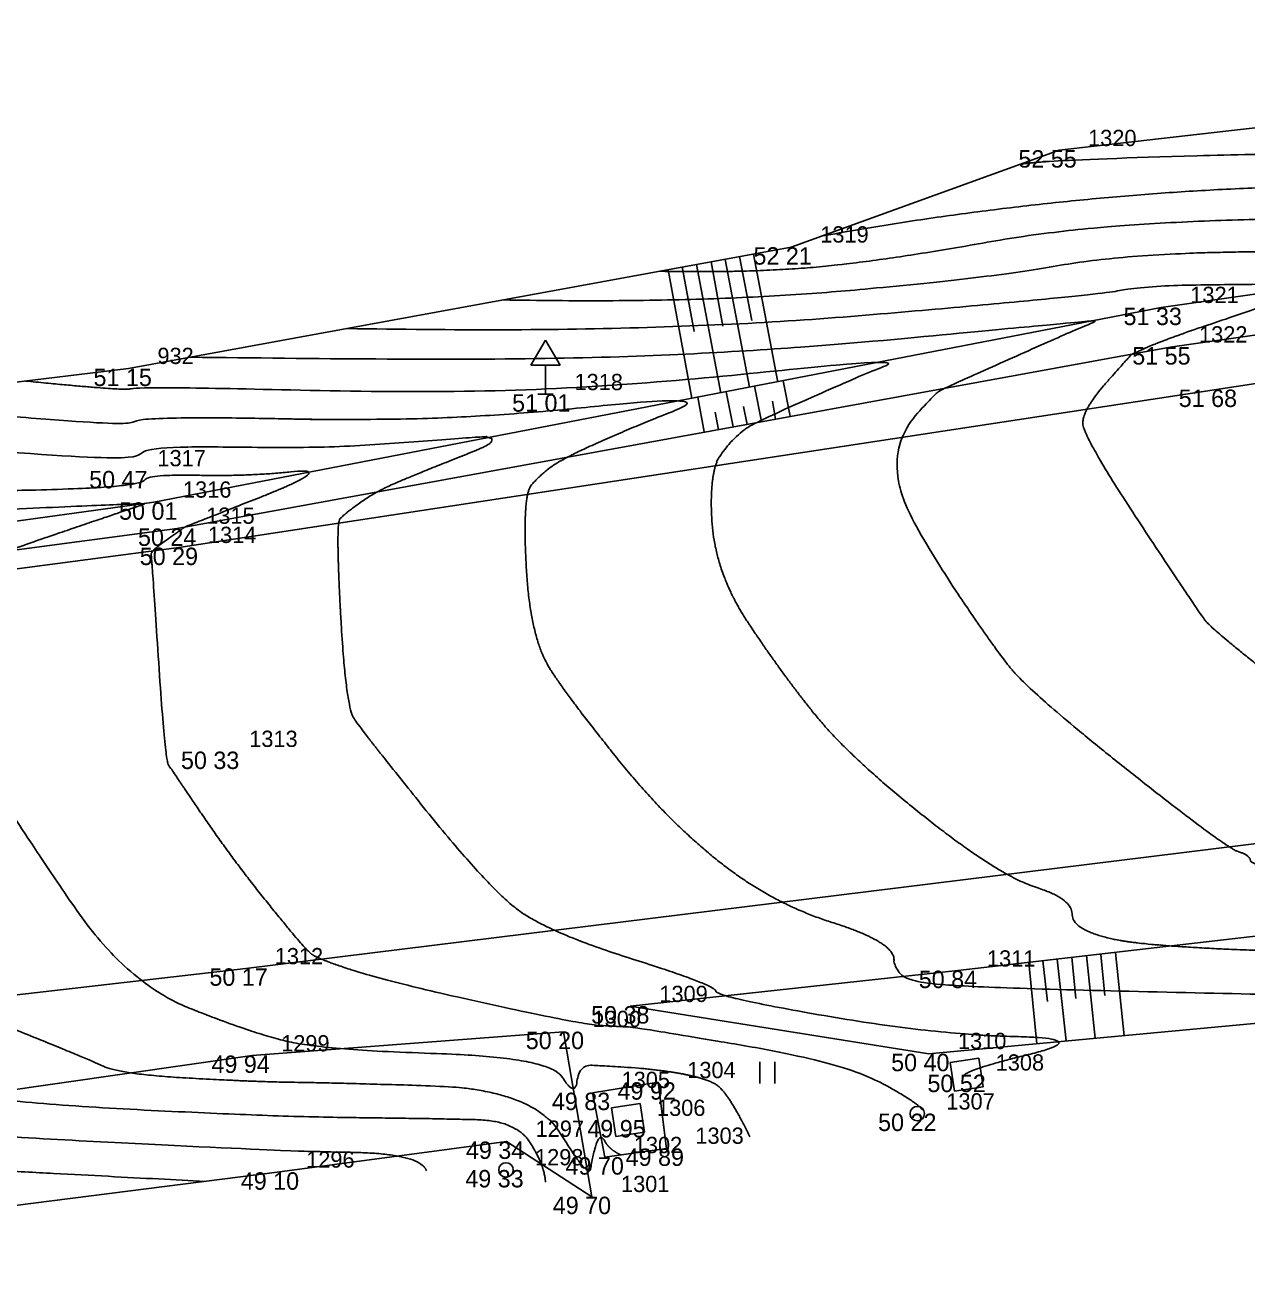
# Model space of a CAD drawing. Extents: x -704017 to -701500, y -1008977 to -1008450.
# Drawn here: x -703029.99 to -703008.96, y -1008832.08 to -1008810.37 of the extents above; entities that cross this region are included whole.
import ezdxf

# ---------------------------------------------------------------- set-up
doc = ezdxf.new("R2010")
doc.units = 0
for name, color, linetype in [('Z_bet_konstrukce', 7, 'Continuous'), ('Z_body', 7, 'Continuous'), ('Z_body_cisla', 7, 'Continuous'), ('Z_body_vysky', 7, 'Continuous'), ('Z_dopravni_znaceni', 7, 'Continuous'), ('Z_komunikace', 7, 'Continuous'), ('Z_popis', 7, 'Continuous'), ('Z_site_znaky_nerozlisene', 7, 'Continuous'), ('Z_sloupky', 7, 'Continuous'), ('Z_teren_hrany_paty', 7, 'Continuous'), ('Z_vrstevnice_hlavni', 7, 'Continuous'), ('Z_vrstevnice_vedlejsi', 7, 'Continuous')]:
    doc.layers.add(name, color=color, linetype=linetype)

# ---------------------------------------------------------------- blocks, each defined once
blk = doc.blocks.new('POINT_DISPLAY')
blk.add_line((0, 0), (0, 0))
blk = doc.blocks.new('Z306')
for p, q in [((-0.13, 0.17), (-0.13, -0.2)), ((0.13, 0.17), (0.13, -0.2))]:
    blk.add_line(p, q)
blk = doc.blocks.new('Z527')
for p, q in [((0, 0.93), (-0.25, 0.5)), ((0.25, 0.5), (0, 0.93)), ((-0.25, 0.5), (0.25, 0.5)), ((0, 0), (0, 0.5)), ((-0.13, 0), (0.13, 0))]:
    blk.add_line(p, q)
blk = doc.blocks.new('Z15')
blk.add_circle((0, 0), 0.125)
blk = doc.blocks.new('Z608')
for p, q in [((0.25, 0.25), (-0.25, 0.25)), ((-0.25, 0.25), (-0.25, -0.25)), ((0.25, -0.25), (0.25, 0.25)), ((-0.25, -0.25), (0.25, -0.25))]:
    blk.add_line(p, q)

msp = doc.modelspace()

# ---------------------------------------------------------------- linework, layer by layer
at = {"layer": 'Z_bet_konstrukce'}
for p, q in [((-703019.09, -1008828.56), (-703020.22, -1008828.74)), ((-703020.22, -1008828.74), (-703020.01, -1008829.85)), ((-703018.95, -1008829.7), (-703019.09, -1008828.56)), ((-703020.01, -1008829.85), (-703018.95, -1008829.7))]:
    msp.add_line(p, q, dxfattribs=at)
at = {"layer": 'Z_komunikace'}
for p, q in [((-703009.48, -1008816.64), (-702992.24, -1008814)), ((-703027.34, -1008819.36), (-703009.48, -1008816.64)), ((-703042.28, -1008821.32), (-703027.34, -1008819.36)), ((-703026.19, -1008826.6), (-703007.3, -1008824.27)), ((-703041.16, -1008828.33), (-703026.19, -1008826.6))]:
    msp.add_line(p, q, dxfattribs=at)
at = {"layer": 'Z_teren_hrany_paty'}
for p, q in [((-703012.19, -1008812.52), (-702993.37, -1008810.37)), ((-703016.8, -1008814.19), (-703012.19, -1008812.52)), ((-703010.43, -1008815.23), (-702992.71, -1008812.69)), ((-703010.28, -1008815.91), (-702992.51, -1008813.37)), ((-703016.8, -1008814.19), (-703028.21, -1008816.28)), ((-703017.94, -1008814.4), (-703017.52, -1008816.6)), ((-703017.69, -1008814.35), (-703017.48, -1008815.45)), ((-703017.45, -1008814.31), (-703017.03, -1008816.51)), ((-703018.92, -1008814.58), (-703018.51, -1008816.79)), ((-703018.68, -1008814.53), (-703018.47, -1008815.64)), ((-703018.43, -1008814.49), (-703018.01, -1008816.7)), ((-703018.18, -1008814.44), (-703017.98, -1008815.55)), ((-703027.77, -1008818.58), (-703010.43, -1008815.23)), ((-703027.37, -1008819.03), (-703010.28, -1008815.91)), ((-703028.21, -1008816.28), (-703042.63, -1008818.01)), ((-703017.31, -1008817.19), (-703017.43, -1008816.58)), ((-703016.82, -1008817.1), (-703016.94, -1008816.49)), ((-703018.3, -1008817.37), (-703018.41, -1008816.77)), ((-703017.8, -1008817.28), (-703017.92, -1008816.68)), ((-703017.56, -1008817.24), (-703017.62, -1008816.93)), ((-703017.07, -1008817.15), (-703017.12, -1008816.84)), ((-703018.05, -1008817.33), (-703018.11, -1008817.03)), ((-703042.44, -1008820.6), (-703027.77, -1008818.58)), ((-703042.38, -1008821.04), (-703027.37, -1008819.03)), ((-703013.93, -1008826.64), (-703005.12, -1008825.62)), ((-703011.22, -1008826.33), (-703011.07, -1008827.76)), ((-703012.71, -1008826.5), (-703012.57, -1008827.9)), ((-703012.47, -1008826.47), (-703012.39, -1008827.17)), ((-703012.22, -1008826.44), (-703012.07, -1008827.85)), ((-703011.97, -1008826.41), (-703011.9, -1008827.12)), ((-703011.72, -1008826.38), (-703011.57, -1008827.8)), ((-703011.47, -1008826.36), (-703011.4, -1008827.07)), ((-703019.57, -1008827.25), (-703013.93, -1008826.64)), ((-703014.43, -1008828.07), (-703004.97, -1008827.19)), ((-703019.57, -1008827.25), (-703014.43, -1008828.07)), ((-703026.08, -1008828.1), (-703020.72, -1008827.69)), ((-703020.72, -1008827.69), (-703020.23, -1008830.53)), ((-703040.99, -1008830.23), (-703026.08, -1008828.1)), ((-703025.65, -1008830.11), (-703021.7, -1008829.58)), ((-703021.7, -1008829.58), (-703020.23, -1008830.53)), ((-703041.27, -1008832.08), (-703025.65, -1008830.11))]:
    msp.add_line(p, q, dxfattribs=at)
at = {"layer": 'Z_vrstevnice_hlavni'}
for points in [[(-703019.06, -1008814.604), (-703017.54, -1008814.633), (-703015.28, -1008814.438), (-703011.397, -1008813.742), (-703004.908, -1008813.657), (-702998.903, -1008813.578), (-703000.519, -1008814.121), (-703002.44, -1008814.789), (-703003.378, -1008815.464), (-703003.548, -1008815.732), (-702998.004, -1008820.258), (-702997.695, -1008821.268), (-702996.146, -1008822.171), (-702993.495, -1008822.563), (-702992.572, -1008822.684), (-702991.407, -1008822.66), (-702991.346, -1008822.668), (-702990.898, -1008822.601), (-702977.897, -1008821.529)], [(-703029.983, -1008816.493), (-703028.21, -1008816.668), (-703028.152, -1008816.583), (-703021.097, -1008816.739), (-703014.765, -1008816.068), (-703015.559, -1008816.38), (-703017.455, -1008817.22), (-703017.727, -1008817.416), (-703018.217, -1008817.971), (-703018.119, -1008819.778), (-703016.98, -1008821.504), (-703015.806, -1008822.959), (-703013.232, -1008825.002), (-703011.963, -1008825.402), (-703011.966, -1008825.938), (-703010.574, -1008826.251), (-703005.046, -1008826.39), (-703003.293, -1008826.722), (-703002.423, -1008826.89), (-703001.685, -1008827.133), (-702999.664, -1008826.653), (-702998.893, -1008826.413), (-702998.118, -1008826.423), (-702995.728, -1008826.499)], [(-703041.803, -1008817.911), (-703040.761, -1008818.014), (-703034.452, -1008818.699), (-703032.364, -1008818.787), (-703027.898, -1008818.598), (-703027.919, -1008818.605), (-703030.347, -1008819.429), (-703030.428, -1008819.5), (-703030.891, -1008819.826), (-703030.728, -1008820.652), (-703030.548, -1008823.382), (-703030.08, -1008824.166), (-703028.259, -1008826.839), (-703026.109, -1008827.709), (-703024.843, -1008828.005), (-703020.948, -1008828.13), (-703020.524, -1008828.826), (-703020.45, -1008828.258), (-703020.019, -1008828.279), (-703019.173, -1008828.332), (-703018.313, -1008828.478), (-703017.901, -1008828.704), (-703017.51, -1008829.5)], [(-703051.184, -1008818.885), (-703048.461, -1008819.367), (-703042.465, -1008820.261), (-703042.435, -1008820.325), (-703041.203, -1008820.377), (-703040.654, -1008820.354), (-703042.391, -1008820.962), (-703042.725, -1008821.069), (-703042.737, -1008821.084), (-703043.096, -1008821.406), (-703042.438, -1008824.768), (-703042.407, -1008824.918), (-703041.435, -1008826.585), (-703040.533, -1008828.094), (-703040.43, -1008828.246), (-703040.255, -1008828.316), (-703037.292, -1008829.702), (-703029.391, -1008830.139), (-703026.89, -1008830.266)]]:
    msp.add_open_spline(points, degree=2, dxfattribs=at)
at = {"layer": 'Z_vrstevnice_vedlejsi'}
for points in [[(-703012.868, -1008812.766), (-703012.118, -1008812.631), (-703000.787, -1008812.483), (-702992.799, -1008812.378), (-702991.56, -1008812.338), (-702989.974, -1008812.323), (-702992.577, -1008813.143), (-702993.73, -1008813.544), (-702993.845, -1008813.627), (-702994.279, -1008814.312), (-702993.279, -1008815.128), (-702992.418, -1008817.943), (-702991.738, -1008818.339), (-702988.386, -1008819.881), (-702987.629, -1008820.459), (-702986.513, -1008820.608), (-702983.835, -1008820.955), (-702976.635, -1008820.369), (-702968.352, -1008819.557), (-702964.643, -1008819.189), (-702961.566, -1008818.877)], [(-703016.258, -1008813.994), (-703011.757, -1008813.186), (-703002.848, -1008813.07), (-702994.602, -1008812.961), (-702995.096, -1008813.127), (-702998.085, -1008814.167), (-702998.612, -1008814.546), (-702998.914, -1008815.022), (-702995.642, -1008817.693), (-702995.056, -1008819.605), (-702992.125, -1008821.315), (-702991.097, -1008821.467), (-702988.276, -1008821.833), (-702976.575, -1008820.881), (-702969.113, -1008820.15)], [(-703021.752, -1008815.097), (-703018.422, -1008815.16), (-703013.47, -1008814.734), (-703011.036, -1008814.297), (-703006.969, -1008814.244), (-703003.204, -1008814.194), (-703005.942, -1008815.115), (-703006.796, -1008815.412), (-703008.145, -1008816.383), (-703008.182, -1008816.441), (-703000.367, -1008822.822), (-703000.333, -1008822.93), (-703000.167, -1008823.027), (-702999.883, -1008823.069), (-702996.653, -1008823.495), (-702992.573, -1008823.41), (-702992.361, -1008823.439), (-702990.792, -1008823.203), (-702983.595, -1008822.61)], [(-703024.443, -1008815.59), (-703019.303, -1008815.687), (-703011.661, -1008815.029), (-703010.675, -1008814.852), (-703009.029, -1008814.831), (-703007.505, -1008814.811), (-703010.314, -1008815.755), (-703010.932, -1008816.029), (-703010.957, -1008816.047), (-703011.793, -1008816.992), (-703011.767, -1008817.471), (-703009.778, -1008820.485), (-703009.551, -1008820.766), (-703007.675, -1008822.255), (-703004.953, -1008823.868), (-703001.217, -1008824.238), (-703001.026, -1008824.267), (-703000.734, -1008824.305), (-702993.74, -1008824.16), (-702993.376, -1008824.21), (-702990.685, -1008823.805), (-702989.293, -1008823.691)], [(-703027.134, -1008816.083), (-703020.184, -1008816.214), (-703013.08, -1008815.603), (-703011.481, -1008815.433), (-703011.673, -1008815.509), (-703014.194, -1008816.625), (-703014.342, -1008816.731), (-703015.005, -1008817.481), (-703014.943, -1008818.624), (-703013.379, -1008820.994), (-703012.679, -1008821.863), (-703009.33, -1008824.52), (-703008.895, -1008824.657), (-703008.896, -1008824.841), (-703005.33, -1008825.644), (-703005.117, -1008825.65), (-703005.05, -1008825.662), (-703004.985, -1008825.675), (-703005.313, -1008825.265), (-703001.892, -1008825.637), (-703000.469, -1008825.247), (-703000.324, -1008825.25), (-702999.638, -1008825.311), (-702995.485, -1008824.922), (-702994.907, -1008824.91), (-702994.567, -1008824.957), (-702994.531, -1008825.005), (-702994.308, -1008825.005), (-702992.848, -1008825.051)], [(-703032.938, -1008816.847), (-703028.21, -1008817.315), (-703028.056, -1008817.087), (-703022.782, -1008817.204), (-703018.049, -1008816.702), (-703019.444, -1008817.252), (-703020.717, -1008817.815), (-703021.112, -1008818.1), (-703021.429, -1008818.46), (-703021.294, -1008820.932), (-703020.581, -1008822.014), (-703018.934, -1008824.056), (-703017.135, -1008825.483), (-703015.03, -1008826.147), (-703015.033, -1008826.759), (-703014.032, -1008826.932), (-703006.599, -1008827.09), (-703004.976, -1008827.131), (-703004.634, -1008827.195)], [(-703035.893, -1008817.202), (-703028.21, -1008817.962), (-703027.959, -1008817.591), (-703024.467, -1008817.669), (-703021.333, -1008817.336), (-703023.329, -1008818.124), (-703023.978, -1008818.411), (-703024.497, -1008818.785), (-703024.642, -1008818.949), (-703024.47, -1008822.085), (-703024.181, -1008822.523), (-703022.062, -1008825.153), (-703021.038, -1008825.965), (-703018.098, -1008826.892), (-703018.099, -1008827.091), (-703014.316, -1008827.745), (-703011.563, -1008827.803), (-703013.888, -1008828.37), (-703013.837, -1008828.475)], [(-703038.848, -1008817.556), (-703034.085, -1008818.028), (-703031.132, -1008818.348), (-703030.154, -1008818.39), (-703028, -1008818.298), (-703027.863, -1008818.096), (-703026.152, -1008818.134), (-703024.617, -1008817.971), (-703027.215, -1008818.995), (-703027.24, -1008819.006), (-703027.364, -1008819.096), (-703027.83, -1008819.424), (-703027.807, -1008819.538), (-703027.58, -1008822.994), (-703027.466, -1008823.184), (-703026.41, -1008824.735), (-703025.189, -1008826.249), (-703024.941, -1008826.446), (-703023.668, -1008826.848), (-703020.401, -1008827.568), (-703019.724, -1008827.602), (-703019.434, -1008827.62), (-703015.886, -1008828.223), (-703014.597, -1008828.928), (-703014.545, -1008829.033)], [(-703044.286, -1008818.179), (-703043.759, -1008818.273), (-703042.598, -1008818.446), (-703042.559, -1008818.53), (-703037.772, -1008819.049), (-703034.574, -1008819.185), (-703031.087, -1008819.037), (-703031.646, -1008819.233), (-703033.448, -1008819.844), (-703033.614, -1008819.989), (-703033.953, -1008820.228), (-703033.649, -1008821.766), (-703033.517, -1008823.77), (-703032.693, -1008825.148), (-703031.302, -1008827.191), (-703028.945, -1008828.144), (-703028.346, -1008828.424), (-703025.983, -1008828.555), (-703024.693, -1008828.569), (-703021.233, -1008828.679), (-703020.279, -1008830.246), (-703020.226, -1008829.842), (-703020.091, -1008829.423), (-703019.93, -1008829.722), (-703019.731, -1008829.811)], [(-703046.585, -1008818.415), (-703045.326, -1008818.637), (-703042.554, -1008819.051), (-703042.46, -1008819.251), (-703041.092, -1008819.4), (-703036.783, -1008819.582), (-703034.276, -1008819.476), (-703035.373, -1008819.86), (-703036.55, -1008820.259), (-703036.8, -1008820.478), (-703037.014, -1008820.629), (-703036.57, -1008822.88), (-703036.485, -1008824.157), (-703035.306, -1008826.13), (-703034.344, -1008827.542), (-703032.715, -1008828.201), (-703031.328, -1008828.85), (-703025.855, -1008829.153), (-703022.868, -1008829.185), (-703021.518, -1008829.228), (-703021.047, -1008830.002), (-703021.03, -1008830.281)], [(-703048.885, -1008818.65), (-703046.894, -1008819.002), (-703042.509, -1008819.656), (-703042.426, -1008819.834), (-703038.993, -1008819.98), (-703037.465, -1008819.915), (-703039.1, -1008820.488), (-703039.651, -1008820.675), (-703039.986, -1008820.968), (-703040.076, -1008821.031), (-703039.49, -1008823.993), (-703039.454, -1008824.545), (-703037.919, -1008827.112), (-703037.387, -1008827.894), (-703036.485, -1008828.259), (-703034.31, -1008829.276), (-703025.727, -1008829.751), (-703023.181, -1008829.779), (-703023.08, -1008830.084)]]:
    msp.add_open_spline(points, degree=2, dxfattribs=at)

# ---------------------------------------------------------------- block references
at = {"layer": 'Z_body'}
for p in [(-703012.19, -1008812.52), (-703016.8, -1008814.19), (-703010.43, -1008815.23), (-703010.28, -1008815.91), (-703028.21, -1008816.28), (-703021.03, -1008816.72), (-703009.48, -1008816.64), (-703028.21, -1008818.04), (-703027.77, -1008818.58), (-703027.37, -1008819.03), (-703027.34, -1008819.36), (-703026.63, -1008822.87), (-703026.19, -1008826.6), (-703013.93, -1008826.64), (-703019.57, -1008827.25), (-703020.72, -1008827.69), (-703014.43, -1008828.07), (-703026.08, -1008828.1), (-703013.78, -1008828.43), (-703020.22, -1008828.74), (-703019.09, -1008828.56), (-703014.63, -1008829.1), (-703019.61, -1008829.21), (-703021.7, -1008829.58), (-703018.95, -1008829.7), (-703020.01, -1008829.85), (-703025.65, -1008830.11), (-703021.71, -1008830.07), (-703020.23, -1008830.53)]:
    msp.add_blockref('POINT_DISPLAY', p, dxfattribs=at)
at = {"layer": 'Z_dopravni_znaceni'}
msp.add_blockref('Z527', (-703021.03, -1008816.72), dxfattribs=at)
at = {"layer": 'Z_popis'}
msp.add_blockref('Z306', (-703017.21, -1008828.38), dxfattribs=at)
at = {"layer": 'Z_site_znaky_nerozlisene', "rotation": 9}
for p in [(-703013.78, -1008828.43), (-703019.61, -1008829.21)]:
    msp.add_blockref('Z608', p, dxfattribs=at)
at = {"layer": 'Z_sloupky'}
for p in [(-703014.63, -1008829.1), (-703021.71, -1008830.07)]:
    msp.add_blockref('Z15', p, dxfattribs=at)

# ---------------------------------------------------------------- texts
at = {"layer": 'Z_body_cisla'}
for s, p in [('1320', (-703011.69, -1008812.45)), ('1319', (-703016.3, -1008814.11)), ('1321', (-703009.93, -1008815.15)), ('1322', (-703009.78, -1008815.83)), ('932', (-703027.71, -1008816.2)), ('1318', (-703020.53, -1008816.65)), ('1317', (-703027.71, -1008817.96)), ('1316', (-703027.27, -1008818.5)), ('1315', (-703026.87, -1008818.95)), ('1314', (-703026.84, -1008819.28)), ('1313', (-703026.13, -1008822.79)), ('1312', (-703025.69, -1008826.53)), ('1311', (-703013.43, -1008826.57)), ('1309', (-703019.07, -1008827.18)), ('1300', (-703020.22, -1008827.61)), ('1299', (-703025.58, -1008828.03)), ('1310', (-703013.93, -1008827.99)), ('1308', (-703013.28, -1008828.36)), ('1304', (-703018.59, -1008828.49)), ('1305', (-703019.72, -1008828.66)), ('1307', (-703014.13, -1008829.03)), ('1306', (-703019.11, -1008829.14)), ('1297', (-703021.2, -1008829.5)), ('1303', (-703018.45, -1008829.62)), ('1302', (-703019.51, -1008829.78)), ('1296', (-703025.15, -1008830.03)), ('1298', (-703021.21, -1008829.99)), ('1301', (-703019.73, -1008830.45))]:
    msp.add_text(s, height=0.28, dxfattribs=at).set_placement(p)
at = {"layer": 'Z_body_vysky'}
for s, p in [('52 55', (-703012.89, -1008812.82)), ('52 21', (-703017.45, -1008814.49)), ('51 33', (-703011.08, -1008815.53)), ('51 55', (-703010.93, -1008816.21)), ('51 15', (-703028.81, -1008816.58)), ('51 01', (-703021.605, -1008817.02)), ('51 68', (-703010.13, -1008816.94)), ('50 47', (-703028.885, -1008818.34)), ('50 01', (-703028.37, -1008818.88)), ('50 24', (-703028.045, -1008819.33)), ('50 29', (-703028.015, -1008819.66)), ('50 33', (-703027.305, -1008823.17)), ('50 17', (-703026.815, -1008826.9)), ('50 84', (-703014.605, -1008826.94)), ('50 38', (-703020.245, -1008827.55)), ('50 20', (-703021.37, -1008827.99)), ('49 94', (-703026.78, -1008828.4)), ('50 40', (-703015.08, -1008828.37)), ('50 52', (-703014.455, -1008828.73)), ('49 83', (-703020.92, -1008829.04)), ('49 92', (-703019.79, -1008828.86)), ('50 22', (-703015.305, -1008829.4)), ('49 95', (-703020.31, -1008829.51)), ('49 34', (-703022.4, -1008829.88)), ('49 89', (-703019.65, -1008830)), ('49 70', (-703020.685, -1008830.15)), ('49 10', (-703026.275, -1008830.41)), ('49 33', (-703022.41, -1008830.37)), ('49 70', (-703020.905, -1008830.83))]:
    msp.add_text(s, height=0.3, dxfattribs=at).set_placement(p)

doc.saveas('drawing.dxf')
